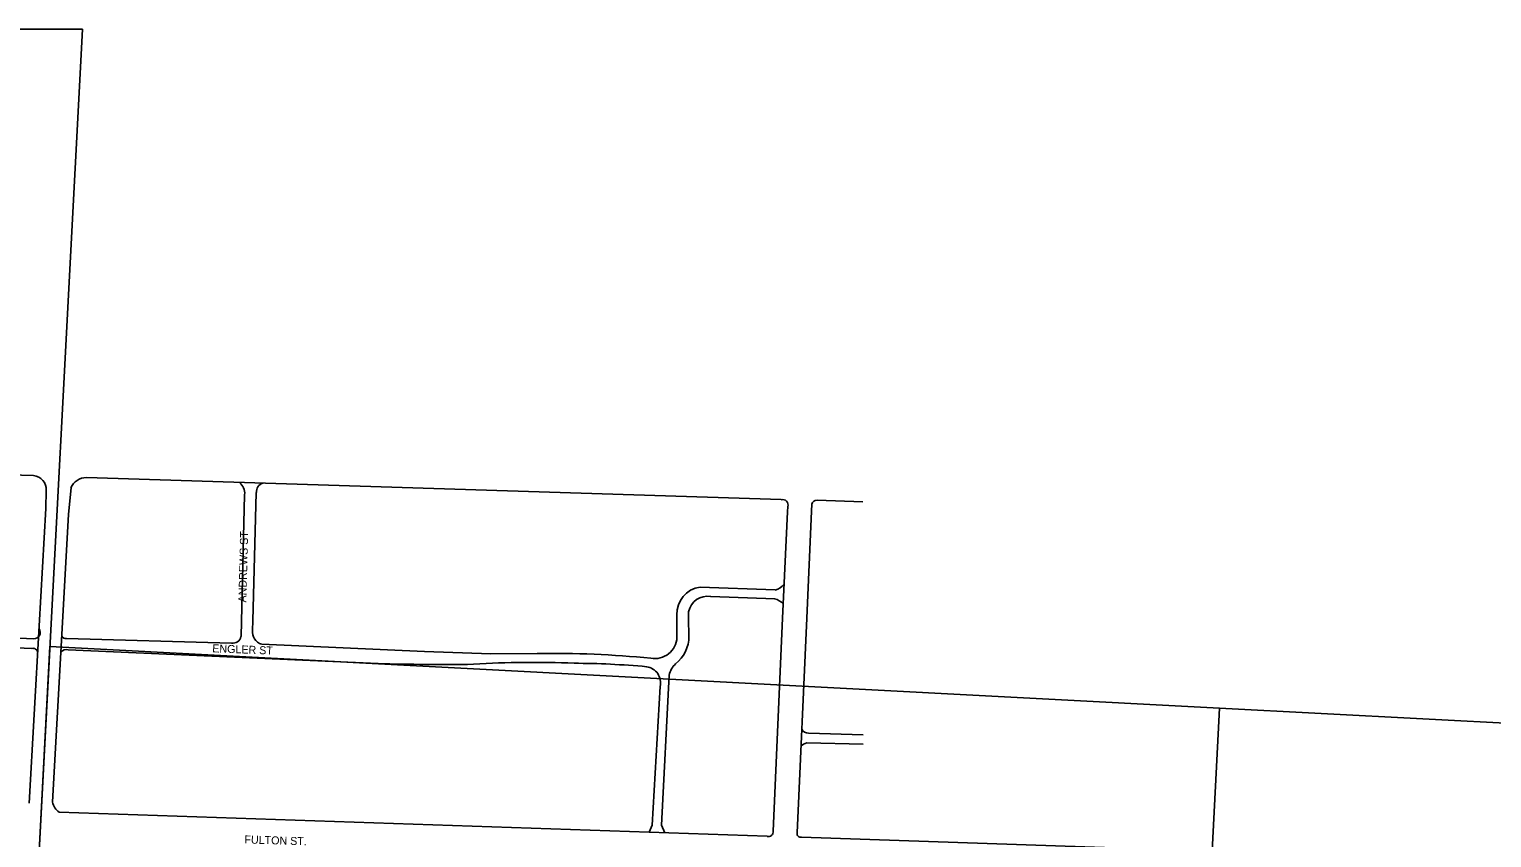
# Model space of a CAD drawing. Extents: x -9648 to 41057, y -12373 to 40276.
# Drawn here: x 11005 to 12833, y -4417 to -3407 of the extents above; entities that cross this region are included whole.
import ezdxf

# ---------------------------------------------------------------- set-up
doc = ezdxf.new("R2010")
doc.units = 0
doc.layers.add('SC_Scratch1', color=7, linetype='Continuous')
doc.layers.add('SH_Data', color=7, linetype='Continuous')

msp = doc.modelspace()

# ---------------------------------------------------------------- linework, layer by layer
at = {"layer": 'SC_Scratch1'}
for p, q in [((9421.5, -3407.4), (11071.8, -3407.2)), ((10990.5, -4947.2), (11071.8, -3407.2)), ((10949.9, -5716.1), (11031.1, -4178.3)), ((11031.1, -4178.3), (12492.9, -4255.5)), ((12492.9, -4255.5), (12411.7, -5793.4)), ((12411.7, -5793.4), (12492.9, -4255.5)), ((12492.9, -4255.5), (12411.7, -5793.4)), ((12492.9, -4255.5), (14069.8, -4338.8))]:
    msp.add_line(p, q, dxfattribs=at)
at = {"layer": 'SH_Data'}
for p, q in [((11057.4, -3980.2), (11054.4, -4013.2)), ((11945, -3994.9), (11076.6, -3967.4)), ((12047.2, -3997.5), (11989.8, -3995.5)), ((11937.5, -4107.7), (11843.6, -4104.2)), ((11856.9, -4115.8), (11936.9, -4118.7)), ((11814.7, -4138.8), (11814.7, -4167)), ((11258.1, -4174.1), (11051.9, -4168.4)), ((11053.9, -4182.4), (11441.1, -4199.6)), ((11979.2, -4286.5), (12047.4, -4288.9)), ((12047.4, -4300.3), (11977.2, -4298.9)), ((11042.6, -4385.4), (11927.6, -4415.5)), ((11970.4, -4416.7), (13142.9, -4456.3))]:
    msp.add_line(p, q, dxfattribs=at)
for points in [[(11010.4, -3964.7), (10873.8, -3961.1), (10648.6, -3953.3)], [(10885, -3961.4), (10880.3, -4149.1), (10880.1, -4162.5), (11010.7, -4168.7)], [(11005.2, -4374.1), (11017.7, -4152.4), (11026, -4006.1), (11026.4, -3983.5)], [(11274.4, -3988.7), (11270.3, -4147.1), (11269.9, -4166.1)], [(11284.3, -4157.9), (11284.5, -4146.5), (11289, -3986.1)], [(11983.2, -4000.7), (11983, -4009.3), (11976.9, -4143), (11964.8, -4411.3)], [(11054.4, -4013.2), (11046.9, -4148.4), (11034.2, -4372.6)], [(11934.8, -4408.9), (11946.8, -4143.1), (11952.8, -4010.1), (11953.2, -4003.5)], [(11829.7, -4165.4), (11829.1, -4143.9), (11829.3, -4135)], [(11008.5, -4180.9), (10874.5, -4174.9), (10868.4, -4372.7)], [(11639.9, -4187.3), (11582.3, -4187.7), (11499.3, -4184.6), (11295.7, -4175.5)], [(11799.5, -4411.2), (11795.6, -4401.8), (11805.1, -4214)], [(11793.9, -4228.2), (11783.6, -4401.8), (11779.9, -4410.5)]]:
    msp.add_lwpolyline(points, dxfattribs=at)
for centre, radius, start, end in [((11008.6, -3982.4), 17.8, 356.6512, 84.2132), ((11076.2, -3987.7), 20.3, 89.0142, 158.4302), ((11257.1, -3987.1), 17.4, 354.5872, 51.3192), ((11300.6, -3985.4), 11.6, 107.9882, 183.3042), ((11946.8, -4001.5), 6.76, 342.1422, 105.1942), ((11989.7, -4002.1), 6.63, 88.9202, 167.6112), ((11848.4, -4137.6), 33.8, 98.1442, 181.9842), ((11930.6, -4084.4), 24.4, 286.2762, 318.0992), ((11853, -4139.7), 24.2, 80.9602, 168.7532), ((11930.9, -4141.3), 23.3, 44.1152, 75.2492), ((11011.2, -4160.9), 7.74, 266.2662, 36.1712), ((11050.9, -4163.4), 5.15, 197.5332, 281.4282), ((11259.7, -4163.8), 10.4, 260.9542, 347.3822), ((11300.3, -4160), 16.2, 172.5312, 253.3982), ((11787, -4165.8), 27.7, 259.8122, 357.4002), ((11786.4, -4166), 43.2, 307.7202, 0.8052), ((11010, -4186.5), 5.84, 8.4672, 105.1672), ((11051.8, -4191.6), 9.44, 77.0972, 137.6672), ((11520.7, -1654.7), 2546.2, 268.2092, 270.8962), ((11635.8, -5439.4), 1241.2, 87.6792, 93.4802), ((11662.6, -5392.8), 1205.7, 84.3132, 91.0802), ((11681.7, -5242.2), 1042.9, 84.7602, 89.7562), ((11773.8, -4223.9), 20.5, 347.9232, 81.4352), ((11829.4, -4218.6), 24.7, 131.8242, 169.2892), ((11978.6, -4277.7), 8.81, 205.0462, 273.3252), ((11978.9, -4310.3), 11.5, 98.7862, 143.3882), ((11054.7, -4368.4), 20.9, 191.8392, 234.7752), ((11929.2, -4410.1), 5.7, 253.5902, 11.4952), ((11969.7, -4411.9), 4.91, 173.6222, 278.5252)]:
    msp.add_arc(centre, radius, start, end, dxfattribs=at)

# ---------------------------------------------------------------- texts
at = {"layer": 'SC_Scratch1'}
for s, rotation, p in [('ANDREWS ST', 88.5022, (11276.5, -4123.5)), ('ENGLER ST', 357.7812, (11233.8, -4185.6)), ('FULTON ST.', 358.2271, (11274, -4424.4))]:
    msp.add_text(s, height=10, rotation=rotation, dxfattribs=at).set_placement(p)

doc.saveas('drawing.dxf')
